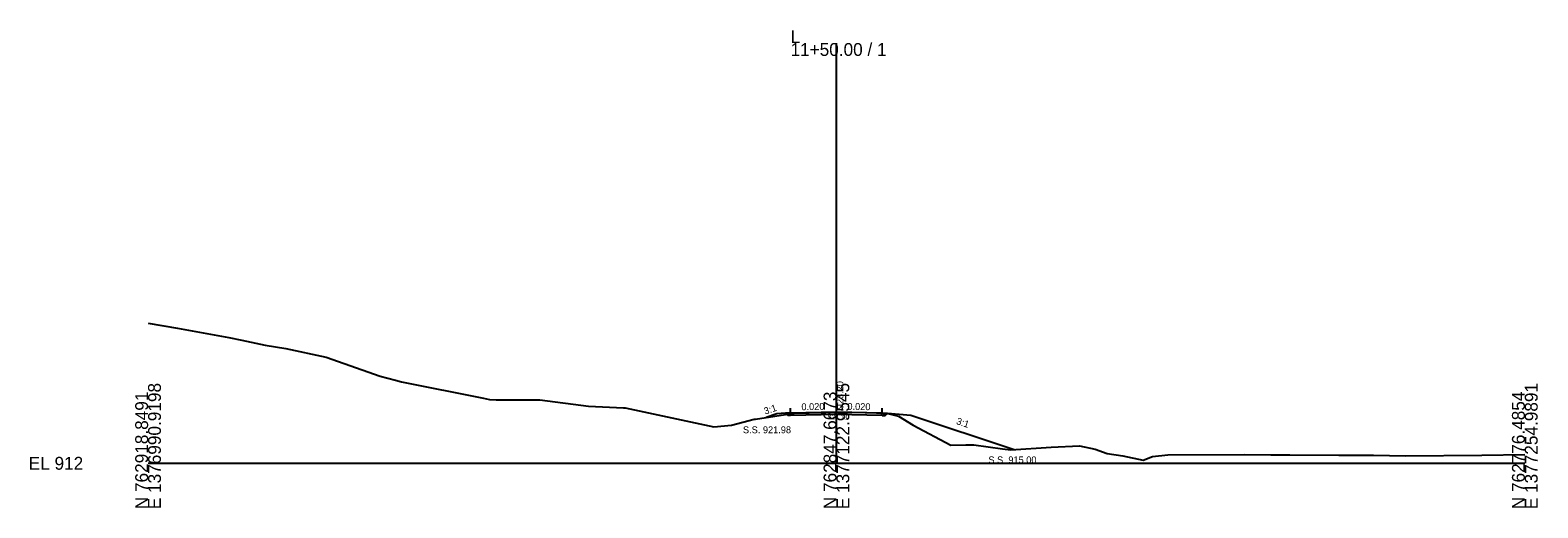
# Model space of a CAD drawing. Extents: x -26 to 303, y -10 to 6523.
# Drawn here: x -25.7 to 302.8, y 1490.3 to 1594.3 of the extents above; entities that cross this region are included whole.
import ezdxf

# ---------------------------------------------------------------- set-up
doc = ezdxf.new("R2010")
doc.units = 0
for name, color, linetype in [('Exist Cross Section Cell', 7, 'Continuous'), ('Exist XS Center Line Elevation Label', 7, 'Continuous'), ('Exist XS Ground Line', 7, 'Continuous'), ('Prop XS Dump Level', 7, 'Continuous'), ('Prop XS Elevation Labels', 7, 'Continuous'), ('Prop XS EOT Tick Mark', 7, 'Continuous'), ('Prop XS Finish Grade', 7, 'Continuous'), ('Prop XS Finish Grade Earthwork', 7, 'Continuous'), ('Prop XS Finish Grade Pavement', 7, 'Continuous'), ('Prop XS Pvmt Edge Slope', 7, 'Continuous'), ('Prop XS SE Text', 7, 'Continuous'), ('Prop XS Side Slope Text', 7, 'Continuous'), ('Prop XS SS Elevation Text', 7, 'Continuous'), ('Prop XS Subgrade Earthwork', 7, 'Continuous')]:
    doc.layers.add(name, color=color, linetype=linetype)

msp = doc.modelspace()

# ---------------------------------------------------------------- linework, layer by layer
at = {"layer": 'Exist Cross Section Cell'}
for p, q in [((150, 1500), (150, 1591.47)), ((0, 1500), (150, 1500)), ((150, 1500), (300, 1500))]:
    msp.add_line(p, q, dxfattribs=at)
at = {"layer": 'Exist XS Ground Line'}
for p, q in [((0, 1530.49), (6.43, 1529.4)), ((6.43, 1529.4), (17.62, 1527.39)), ((17.62, 1527.39), (20.46, 1526.79)), ((20.46, 1526.79), (25.49, 1525.68)), ((25.49, 1525.68), (30.02, 1524.95)), ((30.02, 1524.95), (38.8, 1523.1)), ((38.8, 1523.1), (50.58, 1518.97)), ((50.58, 1518.97), (53.95, 1518.08)), ((53.95, 1518.08), (55.23, 1517.74)), ((55.23, 1517.74), (73.06, 1514.14)), ((73.06, 1514.14), (74.39, 1513.86)), ((74.39, 1513.86), (75.85, 1513.8)), ((75.85, 1513.8), (84.93, 1513.81)), ((84.93, 1513.81), (85.38, 1513.8)), ((85.38, 1513.8), (96, 1512.4)), ((96, 1512.4), (103.62, 1512.09)), ((103.62, 1512.09), (103.98, 1512.04)), ((103.98, 1512.04), (123.29, 1507.91)), ((123.29, 1507.91), (127.13, 1508.31)), ((127.13, 1508.31), (132.06, 1509.57)), ((132.06, 1509.57), (132.36, 1509.63)), ((132.36, 1509.63), (140.79, 1510.89)), ((140.79, 1510.89), (147.31, 1511.07)), ((147.31, 1511.07), (149.78, 1511.13)), ((149.78, 1511.13), (156.29, 1511.02)), ((156.29, 1511.02), (158.7, 1510.99)), ((158.7, 1510.99), (161.49, 1510.78)), ((161.49, 1510.78), (163.51, 1510.22)), ((163.51, 1510.22), (166.75, 1508.32)), ((166.75, 1508.32), (174.95, 1503.96)), ((174.95, 1503.96), (178.18, 1504.03)), ((178.18, 1504.03), (179.93, 1503.98)), ((179.93, 1503.98), (186.17, 1503.11)), ((186.17, 1503.11), (188.02, 1502.95)), ((188.02, 1502.95), (196.77, 1503.52)), ((196.77, 1503.52), (202.96, 1503.78)), ((202.96, 1503.78), (206.38, 1503.08)), ((206.38, 1503.08), (208.98, 1502.14)), ((208.98, 1502.14), (212.44, 1501.63)), ((212.44, 1501.63), (216.81, 1500.65)), ((216.81, 1500.65), (218.88, 1501.5)), ((218.88, 1501.5), (222.18, 1501.86)), ((222.18, 1501.86), (238.88, 1501.91)), ((238.88, 1501.91), (244.64, 1501.85)), ((244.64, 1501.85), (248.79, 1501.81)), ((248.79, 1501.81), (259.49, 1501.78)), ((259.49, 1501.78), (267.06, 1501.77)), ((267.06, 1501.77), (273.97, 1501.65)), ((273.97, 1501.65), (290.61, 1501.77)), ((290.61, 1501.77), (300, 1501.92))]:
    msp.add_line(p, q, dxfattribs=at)
at = {"layer": 'Prop XS Dump Level'}
for p, q in [((140, 1511), (150, 1511.2)), ((150, 1511.2), (160, 1511))]:
    msp.add_line(p, q, dxfattribs=at)
at = {"layer": 'Prop XS EOT Tick Mark'}
for p, q in [((140, 1511), (140, 1512)), ((160, 1511), (160, 1512))]:
    msp.add_line(p, q, dxfattribs=at)
at = {"layer": 'Prop XS Finish Grade'}
for p, q in [((140, 1511), (138.9, 1510.91)), ((160, 1511), (161.1, 1510.91))]:
    msp.add_line(p, q, dxfattribs=at)
at = {"layer": 'Prop XS Finish Grade Earthwork'}
for p, q in [((137, 1510.76), (134.67, 1509.98)), ((138.9, 1510.91), (137, 1510.76)), ((161.1, 1510.91), (166.22, 1510.5)), ((166.22, 1510.5), (188.73, 1503))]:
    msp.add_line(p, q, dxfattribs=at)
at = {"layer": 'Prop XS Finish Grade Pavement'}
for p, q in [((140, 1511), (150, 1511.2)), ((150, 1511.2), (160, 1511))]:
    msp.add_line(p, q, dxfattribs=at)
at = {"layer": 'Prop XS Pvmt Edge Slope'}
for p, q in [((140, 1511), (139.4, 1510.4)), ((160, 1511), (160.6, 1510.4))]:
    msp.add_line(p, q, dxfattribs=at)
at = {"layer": 'Prop XS Subgrade Earthwork'}
for p, q in [((139.4, 1510.4), (138.9, 1510.91)), ((140, 1510.41), (139.4, 1510.4)), ((150, 1510.61), (140, 1510.41)), ((160, 1510.41), (150, 1510.61)), ((160, 1510.41), (160.6, 1510.4)), ((160.6, 1510.4), (161.1, 1510.91))]:
    msp.add_line(p, q, dxfattribs=at)

# ---------------------------------------------------------------- texts
at = {"layer": 'Exist Cross Section Cell'}
for s, p in [('L', (140, 1591.47)), ('11+50.00 / 1', (140, 1588.67)), ('EL 912', (-26, 1498.6))]:
    msp.add_text(s, height=2.8, dxfattribs=at).set_placement(p)
for s, p in [('N 762918.8491', (0, 1490)), ('E 1376990.9198', (2.8, 1490)), ('N 762847.6673', (150, 1490)), ('E 1377122.9545', (152.8, 1490)), ('N 762776.4854', (300, 1490)), ('E 1377254.9891', (302.8, 1490))]:
    msp.add_text(s, height=2.8, rotation=90, dxfattribs=at).set_placement(p)
at = {"layer": 'Exist XS Center Line Elevation Label'}
msp.add_text('923.13', height=0.998, dxfattribs=at).set_placement((148.15, 1509.55))
at = {"layer": 'Prop XS Dump Level'}
for p in [(137, 1510.72), (163, 1510.72)]:
    msp.add_text('Case1', height=0.04, dxfattribs=at).set_placement(p)
at = {"layer": 'Prop XS Elevation Labels'}
msp.add_text(' 923.20', height=1.5, rotation=90, dxfattribs=at).set_placement((151.5, 1511.2))
at = {"layer": 'Prop XS SE Text'}
for rotation, p in [(1.1458, (142.38, 1511.54)), (358.8542, (152.38, 1511.65))]:
    msp.add_text('0.020', height=1.5, rotation=rotation, dxfattribs=at).set_placement(p)
at = {"layer": 'Prop XS Side Slope Text'}
for rotation, p in [(18.4349, (134.48, 1510.58)), (341.5651, (175.99, 1508.57))]:
    msp.add_text('3:1', height=1.5, rotation=rotation, dxfattribs=at).set_placement(p)
at = {"layer": 'Prop XS SS Elevation Text'}
for s, p in [('S.S. 921.98', (129.63, 1506.54)), ('S.S. 915.00', (183.11, 1499.99))]:
    msp.add_text(s, height=1.5, dxfattribs=at).set_placement(p)

doc.saveas('drawing.dxf')
